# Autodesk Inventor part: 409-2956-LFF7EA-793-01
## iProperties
Shininess: 64.0
Angle Display Precision: 2
Document Length Units: 11272
Document Angle Units: 11279
Document Time Units: 11290
Document Mass Units: 11286
Document Length Units Precision: 3
Document Angle Units Precision: 2
Compacted: True
Created: 2002-04
Part Number: 409-2956-LFF7EA-793-01
Description: INLET PIPE STAND ANGLE
Document SubType Name: Modeling
Designer: S. Boerckel
Mass: 1383.8 g
Surface Area: 585.555 cm^2
Volume: 176.281 cm^3
Density: 7.85 g/cm^3
Cost Center: 2 x 2 x 1/4 ANGLE
Material: ASTM A36
Engineer: S. Boerckel
Density: 0.0
Volumn: 0.0
Area: 0.0
PropertySet Name: Model Information
Control State: 0
Master: False
Checked Out: False
length: 11.500 in
SMR: =<COST CENTER> - <MATERIAL>
Author: S. Boerckel
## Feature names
1. Extrusion1
